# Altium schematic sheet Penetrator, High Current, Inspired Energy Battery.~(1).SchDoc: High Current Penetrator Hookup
size B; Organization: Monterey Bay Aquarium Research Institute; Address1: 7700 Sandholdt Rd; Address2: Moss Landing, CA 95039-9644; CompanyName: MBARI; DrawnBy: Hans Thomas; Engineer: Hans Thomas; PageSetup: Record=PageOptions¦CenterHorizontal=True¦CenterVertical=True¦PrintScale=1.09¦XCorrection=1.00¦YCorrection=1.00¦PrintKind=0¦BorderSize=5000000¦LeftOffset=0¦BottomOffset=0¦Orientation=2¦PaperLength=4318¦PaperWidth=2794¦Scale=100¦PaperSource=15¦PrintQuality=-3¦MediaType=1¦DitherType=0¦PrintScaleMode=1¦PaperKind=11x17¦PaperIndex=17
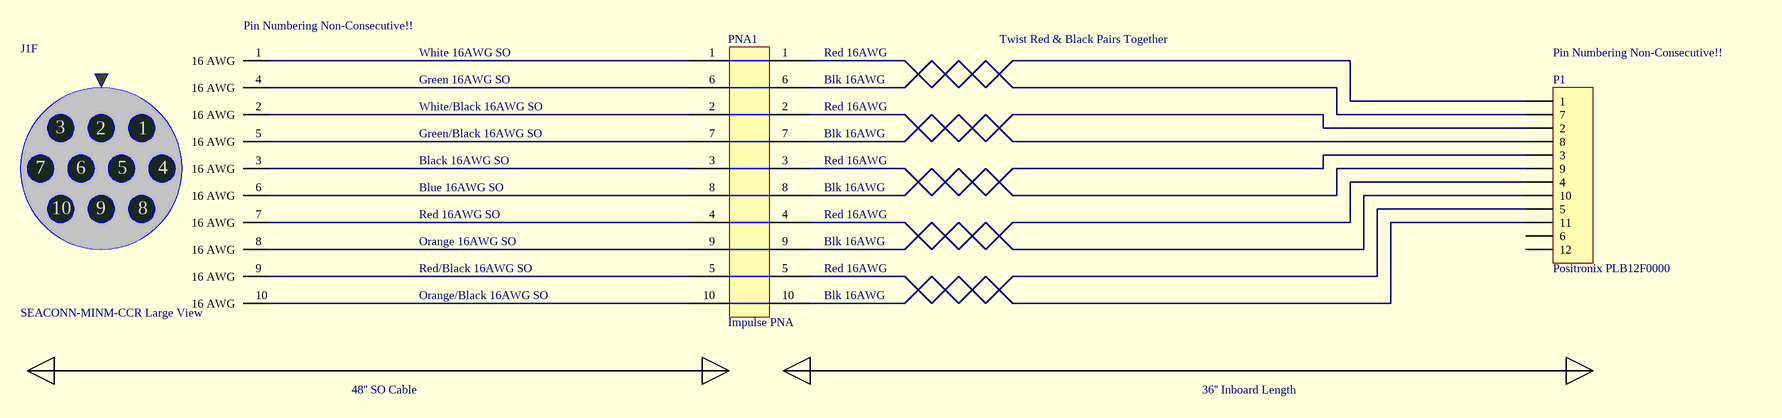
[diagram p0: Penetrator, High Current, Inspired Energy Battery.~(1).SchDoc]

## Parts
J1F  SEACONN-MINM-CCR Large View
P1  Positronix PLB12F0000  [HDR1X12]
PNA1  Impulse PNA

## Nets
NetJ1F_1: J1F.1(16_AWG) PNA1.1
NetJ1F_2: J1F.2(16_AWG) PNA1.2
NetJ1F_3: J1F.3(16_AWG) PNA1.3
NetJ1F_4: J1F.4(16_AWG) PNA1.6
NetJ1F_5: J1F.5(16_AWG) PNA1.7
NetJ1F_6: J1F.6(16_AWG) PNA1.8
NetJ1F_7: J1F.7(16_AWG) PNA1.4
NetJ1F_8: J1F.8(16_AWG) PNA1.9
NetJ1F_9: J1F.9(16_AWG) PNA1.5
NetJ1F_10: J1F.10(16_AWG) PNA1.10
NetP1_1: P1.1 PNA1.1
NetP1_2: P1.2 PNA1.2
NetP1_3: P1.3 PNA1.3
NetP1_4: P1.4 PNA1.4
NetP1_5: P1.5 PNA1.5
NetP1_7: P1.7 PNA1.6
NetP1_8: P1.8 PNA1.7
NetP1_9: P1.9 PNA1.8
NetP1_10: P1.10 PNA1.9
NetP1_11: P1.11 PNA1.10

Not connected (* = marked no-connect by the designer): P1 6 12

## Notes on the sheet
- (near J1F) Pin Numbering Non-Consecutive!!
- White 16AWG SO
- Red 16AWG
- Twist Red & Black Pairs Together
- (near P1) Pin Numbering Non-Consecutive!!
- Green 16AWG SO
- White/Black 16AWG SO
- Blk 16AWG
- Green/Black 16AWG SO
- Black 16AWG SO
- Blue 16AWG SO
- Red 16AWG SO
- Orange 16AWG SO
- Red/Black 16AWG SO
- Orange/Black 16AWG SO
- 48'' SO Cable
- 36'' Inboard Length

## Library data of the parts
P1 = Header 12: Header, 12-Pin
PNA1 = Impulse PNA: Impulse 1''-14 PNA SS R/A Mold w/ 12x#16 Insert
